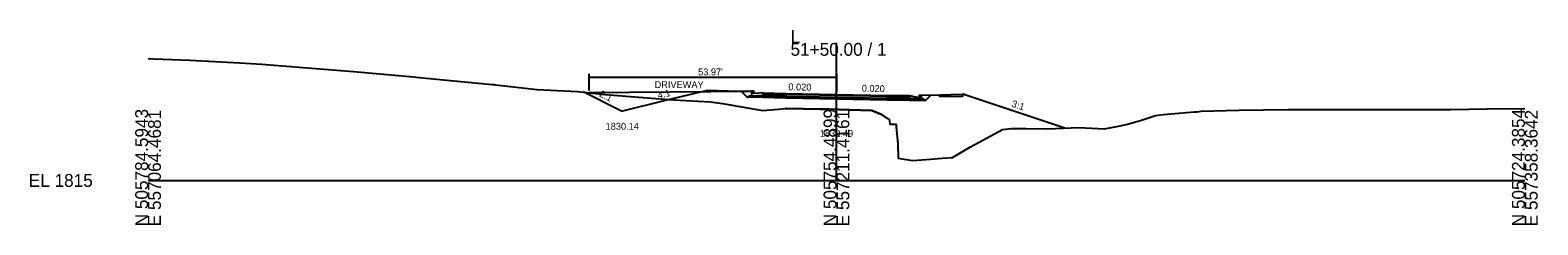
# Model space of a CAD drawing. Extents: x -26 to 4603, y -10 to 4703.
# Drawn here: x 1974.3 to 2302.8, y 670.3 to 712.8 of the extents above; entities that cross this region are included whole.
import ezdxf

# ---------------------------------------------------------------- set-up
doc = ezdxf.new("R2010")
doc.units = 0
for name, color, linetype in [('Default', 7, 'Continuous'), ('Exist Cross Section Cell', 7, 'Continuous'), ('Exist XS Ground Line', 7, 'Continuous'), ('Prop CMT Pvmt Course 1', 7, 'Continuous'), ('Prop CMT Pvmt Course 2', 7, 'Continuous'), ('Prop CMT Pvmt Course 3', 7, 'Continuous'), ('Prop CMT Pvmt Milling', 7, 'Continuous'), ('Prop CMT Shear Line', 7, 'Continuous'), ('Prop CMT Subgrade Earthwork', 7, 'Continuous'), ('Prop Conc 4in Sidewalk', 7, 'Continuous'), ('Prop Conc Curb and Gutter', 7, 'Continuous'), ('Prop Corridor Mesh Bottom', 7, 'Continuous'), ('Prop XS Finish Grade', 7, 'Continuous'), ('Prop XS Label Text', 7, 'Continuous'), ('Prop XS SS Elevation Text', 7, 'Continuous'), ('Scratch_Level_0', 7, 'Continuous')]:
    doc.layers.add(name, color=color, linetype=linetype)

msp = doc.modelspace()

# ---------------------------------------------------------------- linework, layer by layer
at = {"layer": 'Exist Cross Section Cell'}
for p, q in [((2150, 680), (2150, 710)), ((2000, 680), (2150, 680)), ((2150, 680), (2300, 680))]:
    msp.add_line(p, q, dxfattribs=at)
at = {"layer": 'Exist XS Ground Line'}
msp.add_lwpolyline([(2000, 706.63), (2001.28, 706.57), (2009.1, 706.26), (2019.98, 705.67), (2024.77, 705.36), (2031.95, 704.8), (2044.75, 703.78), (2057.01, 702.7), (2059.85, 702.42), (2075.01, 700.95), (2075.35, 700.91), (2075.68, 700.89), (2084.81, 699.81), (2093.58, 699.44), (2099.64, 698.78), (2109.73, 697.93), (2114.51, 697.58), (2122.53, 697.14), (2125.2, 696.79), (2133.97, 695.26), (2134.8, 695.32), (2138.16, 695.65), (2138.89, 695.67), (2139.13, 695.67), (2146.42, 695.56), (2148.44, 695.54), (2150.43, 695.48), (2157.74, 695.25), (2159.82, 694.41), (2161.16, 693.52), (2161.36, 693.48), (2161.51, 693.39), (2161.6, 692.41), (2161.66, 692.28), (2161.77, 692.29), (2162.97, 692.28), (2162.99, 692.14), (2163.04, 691.59), (2163.06, 690.99), (2163.38, 687.97), (2163.48, 684.86), (2166.61, 684.37), (2170.47, 684.63), (2173.04, 684.89), (2175.29, 685.02), (2179.21, 687.35), (2186.22, 691.15), (2188.15, 691.35), (2189.11, 691.34), (2191.26, 691.3), (2195.96, 691.24), (2202.85, 691.57), (2208.38, 691.25), (2211.84, 691.93), (2213.41, 692.27), (2216.45, 693.15), (2219.54, 694.19), (2221.24, 694.36), (2227.97, 694.95), (2228.6, 695), (2229.5, 695.09), (2237.69, 695.32), (2248.41, 695.45), (2248.47, 695.45), (2248.49, 695.45), (2248.53, 695.45), (2261.38, 695.48), (2266.04, 695.48), (2275.31, 695.49), (2283.9, 695.48), (2291.88, 695.62), (2300, 695.7)], dxfattribs=at)
at = {"layer": 'Prop CMT Pvmt Course 1'}
for p, q in [((2139, 699), (2150, 698.78)), ((2150, 698.78), (2161, 698.56))]:
    msp.add_line(p, q, dxfattribs=at)
for points in [[(2134, 699.1), (2139, 699), (2139, 699), (2139, 698.75), (2134, 698.85), (2134, 698.85), (2134, 699.1), (2134, 699.1), (2134, 699.1)], [(2161, 698.56), (2161, 698.56), (2161, 698.56), (2161, 698.31), (2161, 698.31), (2166, 698.21), (2166, 698.46), (2166, 698.46), (2161, 698.56)]]:
    msp.add_lwpolyline(points, dxfattribs=at)
at = {"layer": 'Prop CMT Pvmt Course 2'}
msp.add_line((2161, 698.31), (2139, 698.75), dxfattribs=at)
for points in [[(2134, 698.85), (2139, 698.75), (2139, 698.75), (2139, 698.42), (2134, 698.52), (2134, 698.52), (2134, 698.85), (2134, 698.85), (2134, 698.85)], [(2161, 698.31), (2161, 698.31), (2161, 698.31), (2161, 697.98), (2161, 697.98), (2166, 697.88), (2166, 698.21), (2166, 698.21), (2161, 698.31)]]:
    msp.add_lwpolyline(points, dxfattribs=at)
at = {"layer": 'Prop CMT Pvmt Course 3'}
msp.add_line((2139, 698.42), (2161, 697.98), dxfattribs=at)
for points in [[(2134.02, 698.15), (2130.62, 698.08), (2131, 698.46), (2134, 698.52)], [(2134, 698.52), (2139, 698.42), (2139, 698.42), (2139, 698.05), (2134, 698.15), (2134, 698.15), (2134, 698.52), (2134, 698.52), (2134, 698.52)], [(2161, 697.98), (2161, 697.98), (2161, 697.98), (2161, 697.61), (2161, 697.61), (2166, 697.51), (2166, 697.88), (2166, 697.88), (2161, 697.98)], [(2166, 697.88), (2166, 697.88), (2166, 697.88), (2166, 697.51), (2166, 697.51), (2169.38, 697.44), (2169, 697.82), (2169, 697.82), (2166, 697.88)]]:
    msp.add_lwpolyline(points, dxfattribs=at)
at = {"layer": 'Prop CMT Pvmt Milling'}
for points in [[(2150, 695.49), (2148.44, 695.54), (2148.44, 695.54), (2146.42, 695.56), (2146.42, 695.56), (2139.13, 695.67), (2139.13, 695.67), (2139.13, 695.67), (2139, 695.67)], [(2161, 693.62), (2161, 693.62), (2159.82, 694.41), (2159.82, 694.41), (2159.82, 694.41), (2159.82, 694.41), (2157.74, 695.25), (2157.74, 695.25), (2150.43, 695.48), (2150.43, 695.48), (2150, 695.49)]]:
    msp.add_lwpolyline(points, dxfattribs=at)
at = {"layer": 'Prop CMT Subgrade Earthwork'}
msp.add_line((2139, 698.05), (2161, 697.61), dxfattribs=at)
for points in [[(2134, 698.14), (2130.62, 698.08), (2129.23, 699.46)], [(2134.02, 698.15), (2139, 698.05)], [(2169.38, 697.44), (2161, 697.61), (2161, 697.61)], [(2170.55, 698.6), (2170.55, 698.6), (2169.38, 697.44)]]:
    msp.add_lwpolyline(points, dxfattribs=at)
at = {"layer": 'Prop Conc 4in Sidewalk'}
msp.add_lwpolyline([(2177.5, 698.74), (2172.5, 698.64), (2172.5, 698.64), (2172.49, 698.31), (2177.51, 698.41), (2177.51, 698.41), (2177.5, 698.74), (2177.5, 698.74), (2177.5, 698.74)], dxfattribs=at)
at = {"layer": 'Prop Conc Curb and Gutter'}
for points in [[(2133.07, 699.05), (2132, 698.98), (2132, 699.25), (2132, 699.48), (2131.73, 699.48), (2131.5, 699.48), (2131.5, 699.01), (2131.5, 698.47), (2132.83, 698.5), (2134, 698.52), (2134, 698.83), (2134, 699.1), (2133.07, 699.05)], [(2166, 698.46), (2166, 698.46), (2166, 698.46), (2166, 697.88), (2166, 697.88), (2168.5, 697.83), (2168.5, 698.56), (2168.5, 698.56), (2168.5, 698.56), (2168, 698.56), (2168, 698.56), (2168, 698.06), (2166, 698.46)]]:
    msp.add_lwpolyline(points, dxfattribs=at)
at = {"layer": 'Prop Corridor Mesh Bottom'}
msp.add_lwpolyline([(2166, 698.46), (2166, 698.21)], dxfattribs=at)
at = {"layer": 'Prop XS Finish Grade'}
msp.add_line((2096.03, 699.17), (2131.5, 699.48), dxfattribs=at)
for points in [[(2172.5, 698.64), (2172.5, 698.64), (2168.5, 698.56)], [(2178, 698.75), (2178, 698.75), (2177.5, 698.74)], [(2178, 698.75), (2199.98, 691.43)]]:
    msp.add_lwpolyline(points, dxfattribs=at)
at = {"layer": 'Prop XS Label Text'}
for p, q in [((2096.03, 703.23), (2096.03, 699.63)), ((2150, 703.23), (2150, 699.34)), ((2150, 702.44), (2096.03, 702.44))]:
    msp.add_line(p, q, dxfattribs=at)
at = {"layer": 'Scratch_Level_0'}
for points in [[(2103.16, 695.14), (2103.16, 695.14), (2094.82, 699.31)], [(2103.16, 695.14), (2113.41, 697.68), (2122, 699.67), (2126.44, 699.58), (2131.5, 699.48)]]:
    msp.add_lwpolyline(points, dxfattribs=at)

# ---------------------------------------------------------------- texts
at = {"layer": 'Default'}
msp.add_text('-', height=0.0001, dxfattribs=at).set_placement((2000, 680))
at = {"layer": 'Exist Cross Section Cell'}
for s, p in [('51+50.00 / 1', (2140, 707.2)), ('L', (2140, 710)), ('EL 1815', (1974, 678.6))]:
    msp.add_text(s, height=2.8, dxfattribs=at).set_placement(p)
for s, p in [('N 505784.5943', (2000, 670)), ('E 557064.4681', (2002.8, 670)), ('N 505754.4899', (2150, 670)), ('E 557211.4161', (2152.8, 670)), ('N 505724.3854', (2300, 670)), ('E 557358.3642', (2302.8, 670))]:
    msp.add_text(s, height=2.8, rotation=90, dxfattribs=at).set_placement(p)
at = {"layer": 'Prop CMT Shear Line'}
for p in [(2094.82, 699.3), (2132, 698.98), (2134, 699.1), (2150, 698.78), (2166, 698.46), (2166, 698.46), (2168, 698.06), (2172.5, 698.64), (2177.5, 698.74), (2178, 698.75), (2199.98, 691.43)]:
    msp.add_text('X', height=0.0025, dxfattribs=at).set_placement(p)
at = {"layer": 'Prop XS Label Text'}
for s, rotation, p in [("53.97'", 0.0969, (2119.86, 702.93)), ('DRIVEWAY', 359.9031, (2110.37, 700.15)), ('0.020', 358.8542, (2139.51, 699.69)), ('0.020', 358.8542, (2155.51, 699.37)), ('3:1', 341.5668, (2188.04, 696.14))]:
    msp.add_text(s, height=1.5, rotation=rotation, dxfattribs=at).set_placement(p)
at = {"layer": 'Prop XS SS Elevation Text'}
msp.add_text('1830.49', height=1.5, dxfattribs=at).set_placement((2146.39, 689.52))
at = {"layer": 'Scratch_Level_0'}
for s, rotation, p in [('4:1', 13.5352, (2111.22, 697.8)), ('2:1', 333.4317, (2098.2, 698.4))]:
    msp.add_text(s, height=1.5, rotation=rotation, dxfattribs=at).set_placement(p)
for s, height, p in [('X', 0.0025, (2122, 699.67)), ('X', 0.0025, (2122.5, 699.66)), ('X', 0.0025, (2127.5, 699.56)), ('X', 0.0025, (2103.15, 695.14)), ('1830.14', 1.5, (2099.7, 691.07))]:
    msp.add_text(s, height=height, dxfattribs=at).set_placement(p)

doc.saveas('drawing.dxf')
